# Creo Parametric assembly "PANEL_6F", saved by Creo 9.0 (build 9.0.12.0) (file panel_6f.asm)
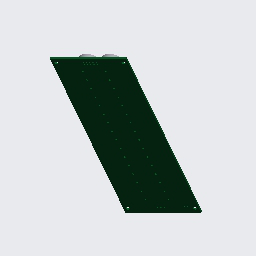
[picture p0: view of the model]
Units: millimeter Newton Second (mmNs); MM, TONNE, SECS

Created from: XX_MMNS_ASM_DESIGN_ABS.ASM

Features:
  1. datum plane "ASM_RIGHT"
  2. datum plane "ASM_TOP"
  3. datum plane "ASM_FRONT"
  4. coordinate system
  5. coordinate system
  6. component "PCB_6F"
  7. coordinate system
  8. component "TX16"
  9. coordinate system
  10. component "TX16"
  11. coordinate system
  12. component "TX16"
  13. coordinate system
  14. component "TX16"
  15. coordinate system
  16. component "TX16"
  17. coordinate system
  18. component "TX16"
  19. coordinate system
  20. component "TX16"
  21. coordinate system
  22. component "TX16"
  23. coordinate system
  24. component "TX16"
  25. coordinate system
  26. component "TX16"
  27. coordinate system
  28. component "TX16"
  29. coordinate system
  30. component "TX16"
  31. coordinate system
  32. component "TX16"
  33. coordinate system
  34. component "TX16"
  35. coordinate system
  36. component "TX16"
  37. coordinate system
  38. component "TX16"

Other named items: ACS0, ACS1, ACS2, ACS3, ACS4, ACS5, ACS6, ACS7, ACS8, ACS9, ACS10, ACS11, ACS12, ACS13, ACS14, ACS15, ACS16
